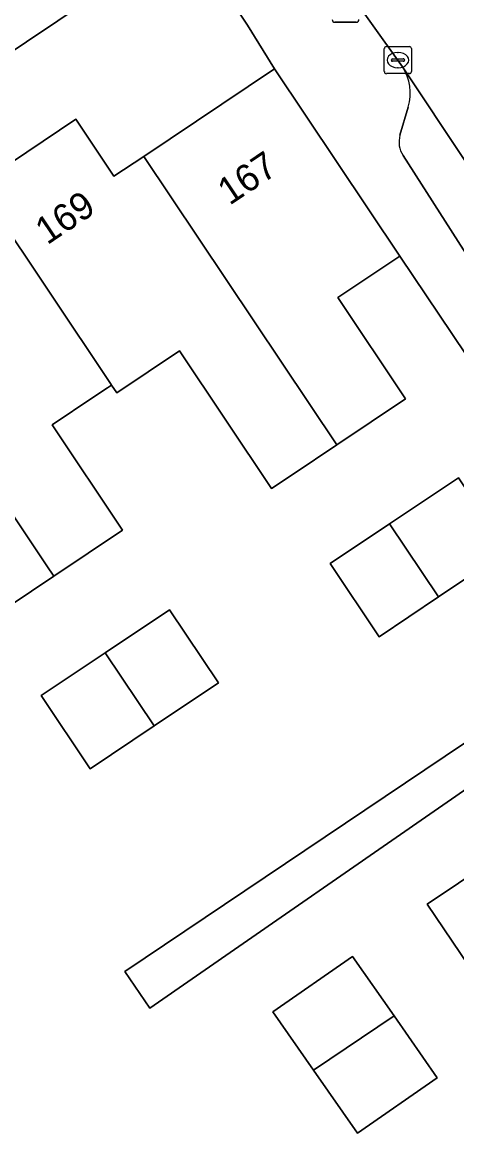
# Model space of a CAD drawing. Extents: x 158352 to 159489, y 383828 to 384603.
# Drawn here: x 158834.96 to 158850.99, y 384167.59 to 384208.76 of the extents above; entities that cross this region are included whole.
import ezdxf

# ---------------------------------------------------------------- set-up
doc = ezdxf.new("R2010")
doc.units = 0
for name, color, linetype in [('IMGEO_Erf', 7, 'Continuous'), ('IMGEO_Kolk', 7, 'Continuous'), ('IMGEO_Lichtmast', 7, 'Continuous'), ('IMGEO_Muur', 7, 'Continuous'), ('IMGEO_Pand', 7, 'Continuous'), ('IMGEO_Pand_nummerreeks', 7, 'Continuous'), ('IMGEO_Parkeervlak_open', 7, 'Continuous'), ('IMGEO_Rijbaan_lokaal_open', 7, 'Continuous'), ('IMGEO_Voetpad_open', 7, 'Continuous')]:
    doc.layers.add(name, color=color, linetype=linetype)

msp = doc.modelspace()

# ---------------------------------------------------------------- linework, layer by layer
at = {"layer": 'IMGEO_Erf'}
for points in [[(158833.309, 384202.752), (158836.934, 384205.178), (158838.343, 384203.073), (158839.443, 384203.809), (158844.268, 384207.036), (158843.27, 384208.645), (158841.042, 384212.024), (158794.638, 384180.916)], [(158856.194, 384189.271), (158848.89, 384200.127), (158846.605, 384198.598), (158849.108, 384194.859), (158846.568, 384193.158), (158844.954, 384192.078), (158844.159, 384191.546), (158840.76, 384196.626), (158838.444, 384195.077), (158838.25, 384195.367), (158838.101, 384195.267), (158837.602, 384194.934), (158836.059, 384193.902), (158838.661, 384190.014), (158836.124, 384188.317), (158833.634, 384186.651)], [(158851.882, 384180.832), (158839.665, 384172.375), (158838.748, 384173.722), (158857.959, 384186.647)], [(158851.438, 384173.932), (158849.91, 384176.206), (158853.411, 384178.559)]]:
    msp.add_lwpolyline(points, dxfattribs=at)
for points in [[(158846.319, 384188.78), (158848.514, 384190.249), (158851.055, 384191.95), (158852.863, 384189.249), (158850.321, 384187.548), (158848.127, 384186.079)], [(158837.462, 384181.205), (158835.654, 384183.906), (158838.017, 384185.488), (158840.39, 384187.076), (158842.198, 384184.375), (158839.824, 384182.786)], [(158845.706, 384170.082), (158844.204, 384172.235), (158847.151, 384174.283), (158848.685, 384172.083), (158850.275, 384169.804), (158847.328, 384167.756)]]:
    msp.add_lwpolyline(points, close=True, dxfattribs=at)
at = {"layer": 'IMGEO_Kolk'}
for p, q in [((158848.323, 384206.935), (158848.323, 384207.787)), ((158848.398, 384207.861), (158849.25, 384207.861)), ((158848.811, 384207.641), (158848.836, 384207.641)), ((158849.324, 384207.787), (158849.324, 384206.935)), ((158848.582, 384207.355), (158848.582, 384207.367)), ((158849.02, 384207.318), (158848.622, 384207.318)), ((158848.625, 384207.404), (158849.023, 384207.404)), ((158849.066, 384207.367), (158849.066, 384207.355)), ((158849.25, 384206.861), (158848.398, 384206.861)), ((158848.834, 384207.081), (158848.809, 384207.081))]:
    msp.add_line(p, q, dxfattribs=at)
for points in [[(158848.323, 384206.935), (158848.323, 384207.787)], [(158848.398, 384207.861), (158849.25, 384207.861)], [(158849.324, 384207.787), (158849.324, 384206.935)], [(158849.25, 384206.861), (158848.398, 384206.861)]]:
    msp.add_lwpolyline(points, dxfattribs=at)
for centre, radius, start, end in [((158848.4, 384207.785), 0.0765, 91.552, 178.448), ((158848.4, 384207.785), 0.0765, 91.552, 178.448), ((158849.248, 384207.785), 0.0765, 1.552, 88.448), ((158849.248, 384207.785), 0.0765, 1.552, 88.448), ((158848.622, 384207.364), 0.0403, 85.8775, 175.7526), ((158848.619, 384207.354), 0.0366, 178.938, 274.7102), ((158849.023, 384207.361), 0.043, 264.8664, 352.4533), ((158849.027, 384207.366), 0.0386, 1.7309, 96.639), ((158848.4, 384206.937), 0.0765, 181.552, 268.448), ((158848.4, 384206.937), 0.0765, 181.552, 268.448), ((158849.248, 384206.937), 0.0765, 271.552, 358.448), ((158849.248, 384206.937), 0.0765, 271.552, 358.448)]:
    msp.add_arc(centre, radius, start, end, dxfattribs=at)
for centre, major_axis, ratio, start_param, end_param in [((158848.81, 384207.361), (-0.387, 0.002), 0.722429, 4.712389, 7.853982), ((158848.835, 384207.361), (-0.39, 0.002), 0.717154, 1.570796, 4.712389)]:
    msp.add_ellipse(centre, major_axis=major_axis, ratio=ratio, start_param=start_param, end_param=end_param, dxfattribs=at)
at = {"layer": 'IMGEO_Lichtmast'}
for p, q in [((158847.288, 384208.756), (158846.498, 384208.756)), ((158846.498, 384208.756), (158847.288, 384208.756))]:
    msp.add_line(p, q, dxfattribs=at)
for centre, start, end in [((158846.498, 384208.856), 180, 270), ((158846.498, 384208.856), 180, 270), ((158847.288, 384208.856), 270, 0), ((158847.288, 384208.856), 270, 0)]:
    msp.add_arc(centre, 0.1, start, end, dxfattribs=at)
at = {"layer": 'IMGEO_Muur'}
msp.add_lwpolyline([(158848.89, 384200.127), (158856.194, 384189.271)], dxfattribs=at)
at = {"layer": 'IMGEO_Pand'}
for points in [[(158839.443, 384203.809), (158846.568, 384193.158), (158849.108, 384194.859), (158846.605, 384198.598), (158848.89, 384200.127), (158844.268, 384207.036)], [(158839.443, 384203.809), (158838.343, 384203.073), (158836.934, 384205.178), (158833.309, 384202.752), (158833.777, 384202.052), (158838.209, 384195.428), (158838.25, 384195.367), (158838.444, 384195.077), (158840.76, 384196.626), (158844.159, 384191.546), (158844.954, 384192.078), (158846.568, 384193.158)], [(158833.777, 384202.052), (158833.598, 384201.932), (158833.086, 384201.589), (158829.052, 384198.891), (158835.871, 384188.696), (158836.124, 384188.317), (158838.661, 384190.014), (158836.059, 384193.902), (158837.602, 384194.934), (158838.101, 384195.267), (158838.25, 384195.367), (158838.209, 384195.428)], [(158824.327, 384195.729), (158828.758, 384189.106), (158828.991, 384188.758), (158831.225, 384190.253), (158833.634, 384186.651), (158836.124, 384188.317), (158835.871, 384188.696), (158829.052, 384198.891)], [(158848.514, 384190.249), (158850.321, 384187.548), (158852.863, 384189.249), (158851.055, 384191.95)], [(158848.514, 384190.249), (158846.319, 384188.78), (158848.127, 384186.079), (158850.321, 384187.548)], [(158839.824, 384182.786), (158842.198, 384184.375), (158840.39, 384187.076), (158838.017, 384185.488)], [(158839.824, 384182.786), (158838.017, 384185.488), (158835.654, 384183.906), (158837.462, 384181.205)], [(158861.106, 384180.426), (158861.009, 384180.57), (158860.667, 384181.079), (158858.049, 384184.975), (158853.899, 384182.187), (158851.882, 384180.832), (158853.411, 384178.559), (158849.91, 384176.206), (158851.438, 384173.932), (158851.682, 384174.096)], [(158845.706, 384170.082), (158848.685, 384172.083), (158847.151, 384174.283), (158844.204, 384172.235)], [(158845.706, 384170.082), (158847.328, 384167.756), (158850.275, 384169.804), (158848.685, 384172.083)]]:
    msp.add_lwpolyline(points, close=True, dxfattribs=at)
at = {"layer": 'IMGEO_Parkeervlak_open'}
for points in [[(158858.586, 384192.689), (158858.439, 384192.912), (158848.992, 384207.115)], [(158849.208, 384205.629), (158848.901, 384204.594)], [(158849.015, 384203.839), (158855.509, 384193.706)]]:
    msp.add_lwpolyline(points, dxfattribs=at)
for centre, radius, start, end in [((158847.489, 384206.138), 1.793, 343.5168, 33.024), ((158849.765, 384204.338), 0.901, 163.5045, 213.6683)]:
    msp.add_arc(centre, radius, start, end, dxfattribs=at)
at = {"layer": 'IMGEO_Rijbaan_lokaal_open'}
msp.add_lwpolyline([(158851.983, 384208.383), (158851.589, 384208.974), (158851.354, 384209.268), (158848.141, 384213.898), (158847.546, 384214.816), (158844.837, 384213.001), (158845.444, 384212.097), (158848.992, 384207.115), (158858.439, 384192.912), (158858.586, 384192.689), (158860.943, 384189.158), (158863.65, 384190.966), (158861.676, 384193.862)], close=True, dxfattribs=at)
at = {"layer": 'IMGEO_Voetpad_open'}
for points in [[(158848.992, 384207.115), (158845.444, 384212.097), (158844.837, 384213.001), (158843.962, 384214.297), (158841.042, 384212.024), (158843.27, 384208.645), (158844.268, 384207.036), (158848.89, 384200.127), (158856.194, 384189.271), (158857.959, 384186.647), (158858.762, 384185.454), (158861.724, 384181.051), (158861.821, 384180.907), (158864.81, 384176.459), (158864.513, 384176.259), (158864.588, 384176.147), (158865.246, 384175.168), (158867.501, 384171.811), (158870.361, 384167.555), (158870.648, 384167.748), (158870.778, 384167.555)], [(158790.706, 384178.683), (158791.011, 384178.139), (158793.73, 384180.171), (158794.638, 384180.916), (158841.042, 384212.024)], [(158848.901, 384204.594), (158849.208, 384205.629)], [(158855.509, 384193.706), (158849.015, 384203.839)]]:
    msp.add_lwpolyline(points, dxfattribs=at)
msp.add_lwpolyline([(158851.882, 384180.832), (158853.899, 384182.187), (158858.049, 384184.975), (158858.762, 384185.454), (158857.959, 384186.647), (158838.748, 384173.722), (158839.665, 384172.375)], close=True, dxfattribs=at)
for centre, radius, start, end in [((158847.489, 384206.138), 1.793, 343.5168, 33.024), ((158849.765, 384204.338), 0.901, 163.5045, 213.6683)]:
    msp.add_arc(centre, radius, start, end, dxfattribs=at)

# ---------------------------------------------------------------- texts
at = {"layer": 'IMGEO_Pand_nummerreeks'}
for s, rotation, p in [('167', 33.7796, (158842.609, 384201.98)), ('169', 33.8102, (158835.878, 384200.523))]:
    msp.add_text(s, height=1, rotation=rotation, dxfattribs=at).set_placement(p)

doc.saveas('drawing.dxf')
